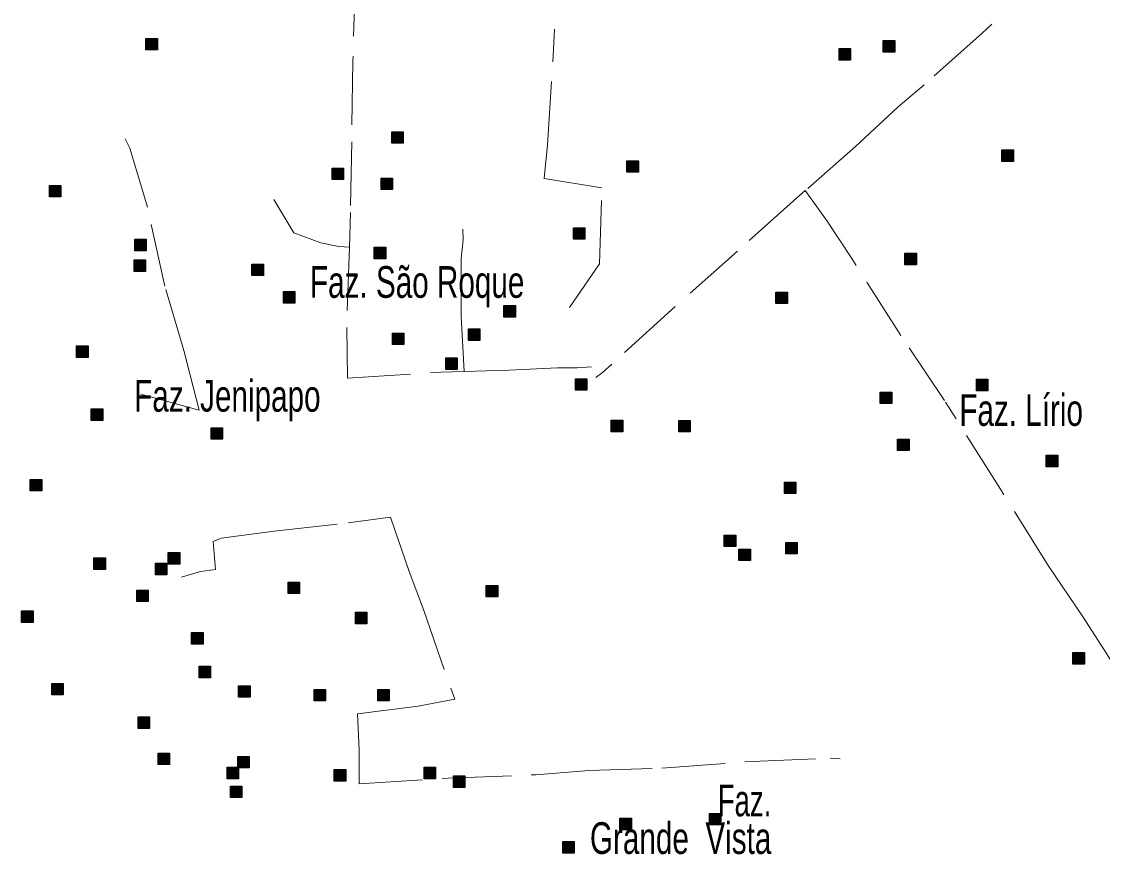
# Model space of a CAD drawing. Extents: x 445.6 to 500, y 8618.1 to 8673.4.
# Drawn here: x 477.45 to 482.9, y 8640.05 to 8644.26 of the extents above; entities that cross this region are included whole.
import ezdxf
from ezdxf.enums import TextEntityAlignment as Align

# ---------------------------------------------------------------- set-up
doc = ezdxf.new("R2010")
doc.units = 0
doc.header["$LTSCALE"] = 0.064
doc.linetypes.add('DOT_DASHED', pattern=[7.7, 5, -1.2, 0.3, -1.2])
doc.layers.add('2', color=7, linetype='Continuous', lineweight=25)
doc.layers.add('22', color=7, linetype='DOT_DASHED', lineweight=13)
doc.layers.add('61', color=7, linetype='Continuous')

msp = doc.modelspace()

# ---------------------------------------------------------------- hatches: boundary and pattern name
at = {"layer": '2'}
for points in [[(478.0733, 8644.173), (478.1313, 8644.173), (478.1313, 8644.115), (478.0733, 8644.115)], [(481.5725, 8644.1218), (481.6305, 8644.1218), (481.6305, 8644.0638), (481.5725, 8644.0638)], [(481.7954, 8644.1625), (481.8534, 8644.1625), (481.8534, 8644.1045), (481.7954, 8644.1045)], [(479.3145, 8643.7016), (479.3725, 8643.7016), (479.3725, 8643.6436), (479.3145, 8643.6436)], [(482.3951, 8643.6102), (482.4531, 8643.6102), (482.4531, 8643.5522), (482.3951, 8643.5522)], [(479.0138, 8643.5186), (479.0718, 8643.5186), (479.0718, 8643.4606), (479.0138, 8643.4606)], [(480.502, 8643.5559), (480.56, 8643.5559), (480.56, 8643.4979), (480.502, 8643.4979)], [(479.2604, 8643.4678), (479.3184, 8643.4678), (479.3184, 8643.4098), (479.2604, 8643.4098)], [(477.5869, 8643.4305), (477.6449, 8643.4305), (477.6449, 8643.3725), (477.5869, 8643.3725)], [(480.2321, 8643.2171), (480.2901, 8643.2171), (480.2901, 8643.1591), (480.2321, 8643.1591)], [(478.0174, 8643.1595), (478.0754, 8643.1595), (478.0754, 8643.1015), (478.0174, 8643.1015)], [(479.2266, 8643.1188), (479.2846, 8643.1188), (479.2846, 8643.0608), (479.2266, 8643.0608)], [(481.9054, 8643.0885), (481.9634, 8643.0885), (481.9634, 8643.0305), (481.9054, 8643.0305)], [(478.014, 8643.0545), (478.072, 8643.0545), (478.072, 8642.9965), (478.014, 8642.9965)], [(478.6085, 8643.0342), (478.6665, 8643.0342), (478.6665, 8642.9762), (478.6085, 8642.9762)], [(478.7673, 8642.8952), (478.8253, 8642.8952), (478.8253, 8642.8372), (478.7673, 8642.8372)], [(481.2535, 8642.892), (481.3115, 8642.892), (481.3115, 8642.834), (481.2535, 8642.834)], [(479.8808, 8642.8242), (479.9388, 8642.8242), (479.9388, 8642.7662), (479.8808, 8642.7662)], [(479.702, 8642.7065), (479.76, 8642.7065), (479.76, 8642.6485), (479.702, 8642.6485)], [(479.3178, 8642.6852), (479.3758, 8642.6852), (479.3758, 8642.6272), (479.3178, 8642.6272)], [(477.7236, 8642.6208), (477.7816, 8642.6208), (477.7816, 8642.5628), (477.7236, 8642.5628)], [(479.587, 8642.5599), (479.645, 8642.5599), (479.645, 8642.5019), (479.587, 8642.5019)], [(480.2422, 8642.4549), (480.3002, 8642.4549), (480.3002, 8642.3969), (480.2422, 8642.3969)], [(482.2658, 8642.4522), (482.3238, 8642.4522), (482.3238, 8642.3942), (482.2658, 8642.3942)], [(481.7804, 8642.3872), (481.8384, 8642.3872), (481.8384, 8642.3292), (481.7804, 8642.3292)], [(477.7979, 8642.3024), (477.8559, 8642.3024), (477.8559, 8642.2444), (477.7979, 8642.2444)], [(478.4025, 8642.2075), (478.4605, 8642.2075), (478.4605, 8642.1495), (478.4025, 8642.1495)], [(480.4228, 8642.2453), (480.4808, 8642.2453), (480.4808, 8642.1873), (480.4228, 8642.1873)], [(480.7637, 8642.2449), (480.8217, 8642.2449), (480.8217, 8642.1869), (480.7637, 8642.1869)], [(481.8682, 8642.15), (481.9262, 8642.15), (481.9262, 8642.092), (481.8682, 8642.092)], [(482.6184, 8642.0687), (482.6764, 8642.0687), (482.6764, 8642.0107), (482.6184, 8642.0107)], [(477.49, 8641.9469), (477.548, 8641.9469), (477.548, 8641.8889), (477.49, 8641.8889)], [(481.2969, 8641.9335), (481.3549, 8641.9335), (481.3549, 8641.8755), (481.2969, 8641.8755)], [(480.9929, 8641.6658), (481.0509, 8641.6658), (481.0509, 8641.6078), (480.9929, 8641.6078)], [(481.3037, 8641.6285), (481.3617, 8641.6285), (481.3617, 8641.5705), (481.3037, 8641.5705)], [(478.186, 8641.5769), (478.244, 8641.5769), (478.244, 8641.5189), (478.186, 8641.5189)], [(481.0672, 8641.5947), (481.1252, 8641.5947), (481.1252, 8641.5367), (481.0672, 8641.5367)], [(477.8109, 8641.5505), (477.8689, 8641.5505), (477.8689, 8641.4925), (477.8109, 8641.4925)], [(478.1216, 8641.5234), (478.1796, 8641.5234), (478.1796, 8641.4654), (478.1216, 8641.4654)], [(478.027, 8641.3879), (478.085, 8641.3879), (478.085, 8641.3299), (478.027, 8641.3299)], [(478.7917, 8641.4287), (478.8497, 8641.4287), (478.8497, 8641.3707), (478.7917, 8641.3707)], [(479.7915, 8641.4118), (479.8495, 8641.4118), (479.8495, 8641.3538), (479.7915, 8641.3538)], [(477.4461, 8641.2829), (477.5041, 8641.2829), (477.5041, 8641.2249), (477.4461, 8641.2249)], [(479.1316, 8641.2761), (479.1896, 8641.2761), (479.1896, 8641.2181), (479.1316, 8641.2181)], [(478.3044, 8641.1733), (478.3624, 8641.1733), (478.3624, 8641.1153), (478.3044, 8641.1153)], [(482.7535, 8641.0727), (482.8115, 8641.0727), (482.8115, 8641.0147), (482.7535, 8641.0147)], [(478.3416, 8641.0037), (478.3996, 8641.0037), (478.3996, 8640.9457), (478.3416, 8640.9457)], [(477.5981, 8640.917), (477.6561, 8640.917), (477.6561, 8640.859), (477.5981, 8640.859)], [(478.5411, 8640.9053), (478.5991, 8640.9053), (478.5991, 8640.8473), (478.5411, 8640.8473)], [(478.9221, 8640.8865), (478.9801, 8640.8865), (478.9801, 8640.8285), (478.9221, 8640.8285)], [(479.2443, 8640.8867), (479.3023, 8640.8867), (479.3023, 8640.8287), (479.2443, 8640.8287)], [(478.0338, 8640.7476), (478.0918, 8640.7476), (478.0918, 8640.6896), (478.0338, 8640.6896)], [(478.1351, 8640.5647), (478.1931, 8640.5647), (478.1931, 8640.5067), (478.1351, 8640.5067)], [(478.5371, 8640.5477), (478.5951, 8640.5477), (478.5951, 8640.4897), (478.5371, 8640.4897)], [(478.483, 8640.4935), (478.541, 8640.4935), (478.541, 8640.4355), (478.483, 8640.4355)], [(479.0246, 8640.4814), (479.0826, 8640.4814), (479.0826, 8640.4234), (479.0246, 8640.4234)], [(479.4774, 8640.4937), (479.5354, 8640.4937), (479.5354, 8640.4357), (479.4774, 8640.4357)], [(479.626, 8640.4496), (479.684, 8640.4496), (479.684, 8640.3916), (479.626, 8640.3916)], [(478.4999, 8640.3987), (478.5579, 8640.3987), (478.5579, 8640.3407), (478.4999, 8640.3407)], [(480.9186, 8640.2599), (480.9766, 8640.2599), (480.9766, 8640.2019), (480.9186, 8640.2019)], [(480.466, 8640.2362), (480.524, 8640.2362), (480.524, 8640.1782), (480.466, 8640.1782)], [(480.1782, 8640.1184), (480.2362, 8640.1184), (480.2362, 8640.0604), (480.1782, 8640.0604)]]:
    msp.add_hatch(color=256, dxfattribs=at).paths.add_polyline_path(points)

# ---------------------------------------------------------------- linework, layer by layer
for points in [[(478.0733, 8644.173), (478.1313, 8644.173), (478.1313, 8644.115), (478.0733, 8644.115)], [(481.5725, 8644.1218), (481.6305, 8644.1218), (481.6305, 8644.0638), (481.5725, 8644.0638)], [(481.7954, 8644.1625), (481.8534, 8644.1625), (481.8534, 8644.1045), (481.7954, 8644.1045)], [(479.3145, 8643.7016), (479.3725, 8643.7016), (479.3725, 8643.6436), (479.3145, 8643.6436)], [(482.3951, 8643.6102), (482.4531, 8643.6102), (482.4531, 8643.5522), (482.3951, 8643.5522)], [(479.0138, 8643.5186), (479.0718, 8643.5186), (479.0718, 8643.4606), (479.0138, 8643.4606)], [(480.502, 8643.5559), (480.56, 8643.5559), (480.56, 8643.4979), (480.502, 8643.4979)], [(479.2604, 8643.4678), (479.3184, 8643.4678), (479.3184, 8643.4098), (479.2604, 8643.4098)], [(477.5869, 8643.4305), (477.6449, 8643.4305), (477.6449, 8643.3725), (477.5869, 8643.3725)], [(480.2321, 8643.2171), (480.2901, 8643.2171), (480.2901, 8643.1591), (480.2321, 8643.1591)], [(478.0174, 8643.1595), (478.0754, 8643.1595), (478.0754, 8643.1015), (478.0174, 8643.1015)], [(479.2266, 8643.1188), (479.2846, 8643.1188), (479.2846, 8643.0608), (479.2266, 8643.0608)], [(481.9054, 8643.0885), (481.9634, 8643.0885), (481.9634, 8643.0305), (481.9054, 8643.0305)], [(478.014, 8643.0545), (478.072, 8643.0545), (478.072, 8642.9965), (478.014, 8642.9965)], [(478.6085, 8643.0342), (478.6665, 8643.0342), (478.6665, 8642.9762), (478.6085, 8642.9762)], [(478.7673, 8642.8952), (478.8253, 8642.8952), (478.8253, 8642.8372), (478.7673, 8642.8372)], [(481.2535, 8642.892), (481.3115, 8642.892), (481.3115, 8642.834), (481.2535, 8642.834)], [(479.8808, 8642.8242), (479.9388, 8642.8242), (479.9388, 8642.7662), (479.8808, 8642.7662)], [(479.702, 8642.7065), (479.76, 8642.7065), (479.76, 8642.6485), (479.702, 8642.6485)], [(479.3178, 8642.6852), (479.3758, 8642.6852), (479.3758, 8642.6272), (479.3178, 8642.6272)], [(477.7236, 8642.6208), (477.7816, 8642.6208), (477.7816, 8642.5628), (477.7236, 8642.5628)], [(479.587, 8642.5599), (479.645, 8642.5599), (479.645, 8642.5019), (479.587, 8642.5019)], [(480.2422, 8642.4549), (480.3002, 8642.4549), (480.3002, 8642.3969), (480.2422, 8642.3969)], [(482.2658, 8642.4522), (482.3238, 8642.4522), (482.3238, 8642.3942), (482.2658, 8642.3942)], [(481.7804, 8642.3872), (481.8384, 8642.3872), (481.8384, 8642.3292), (481.7804, 8642.3292)], [(477.7979, 8642.3024), (477.8559, 8642.3024), (477.8559, 8642.2444), (477.7979, 8642.2444)], [(478.4025, 8642.2075), (478.4605, 8642.2075), (478.4605, 8642.1495), (478.4025, 8642.1495)], [(480.4228, 8642.2453), (480.4808, 8642.2453), (480.4808, 8642.1873), (480.4228, 8642.1873)], [(480.7637, 8642.2449), (480.8217, 8642.2449), (480.8217, 8642.1869), (480.7637, 8642.1869)], [(481.8682, 8642.15), (481.9262, 8642.15), (481.9262, 8642.092), (481.8682, 8642.092)], [(482.6184, 8642.0687), (482.6764, 8642.0687), (482.6764, 8642.0107), (482.6184, 8642.0107)], [(477.49, 8641.9469), (477.548, 8641.9469), (477.548, 8641.8889), (477.49, 8641.8889)], [(481.2969, 8641.9335), (481.3549, 8641.9335), (481.3549, 8641.8755), (481.2969, 8641.8755)], [(480.9929, 8641.6658), (481.0509, 8641.6658), (481.0509, 8641.6078), (480.9929, 8641.6078)], [(481.3037, 8641.6285), (481.3617, 8641.6285), (481.3617, 8641.5705), (481.3037, 8641.5705)], [(478.186, 8641.5769), (478.244, 8641.5769), (478.244, 8641.5189), (478.186, 8641.5189)], [(481.0672, 8641.5947), (481.1252, 8641.5947), (481.1252, 8641.5367), (481.0672, 8641.5367)], [(477.8109, 8641.5505), (477.8689, 8641.5505), (477.8689, 8641.4925), (477.8109, 8641.4925)], [(478.1216, 8641.5234), (478.1796, 8641.5234), (478.1796, 8641.4654), (478.1216, 8641.4654)], [(478.027, 8641.3879), (478.085, 8641.3879), (478.085, 8641.3299), (478.027, 8641.3299)], [(478.7917, 8641.4287), (478.8497, 8641.4287), (478.8497, 8641.3707), (478.7917, 8641.3707)], [(479.7915, 8641.4118), (479.8495, 8641.4118), (479.8495, 8641.3538), (479.7915, 8641.3538)], [(477.4461, 8641.2829), (477.5041, 8641.2829), (477.5041, 8641.2249), (477.4461, 8641.2249)], [(479.1316, 8641.2761), (479.1896, 8641.2761), (479.1896, 8641.2181), (479.1316, 8641.2181)], [(478.3044, 8641.1733), (478.3624, 8641.1733), (478.3624, 8641.1153), (478.3044, 8641.1153)], [(482.7535, 8641.0727), (482.8115, 8641.0727), (482.8115, 8641.0147), (482.7535, 8641.0147)], [(478.3416, 8641.0037), (478.3996, 8641.0037), (478.3996, 8640.9457), (478.3416, 8640.9457)], [(477.5981, 8640.917), (477.6561, 8640.917), (477.6561, 8640.859), (477.5981, 8640.859)], [(478.5411, 8640.9053), (478.5991, 8640.9053), (478.5991, 8640.8473), (478.5411, 8640.8473)], [(478.9221, 8640.8865), (478.9801, 8640.8865), (478.9801, 8640.8285), (478.9221, 8640.8285)], [(479.2443, 8640.8867), (479.3023, 8640.8867), (479.3023, 8640.8287), (479.2443, 8640.8287)], [(478.0338, 8640.7476), (478.0918, 8640.7476), (478.0918, 8640.6896), (478.0338, 8640.6896)], [(478.1351, 8640.5647), (478.1931, 8640.5647), (478.1931, 8640.5067), (478.1351, 8640.5067)], [(478.5371, 8640.5477), (478.5951, 8640.5477), (478.5951, 8640.4897), (478.5371, 8640.4897)], [(478.483, 8640.4935), (478.541, 8640.4935), (478.541, 8640.4355), (478.483, 8640.4355)], [(479.0246, 8640.4814), (479.0826, 8640.4814), (479.0826, 8640.4234), (479.0246, 8640.4234)], [(479.4774, 8640.4937), (479.5354, 8640.4937), (479.5354, 8640.4357), (479.4774, 8640.4357)], [(479.626, 8640.4496), (479.684, 8640.4496), (479.684, 8640.3916), (479.626, 8640.3916)], [(478.4999, 8640.3987), (478.5579, 8640.3987), (478.5579, 8640.3407), (478.4999, 8640.3407)], [(480.9186, 8640.2599), (480.9766, 8640.2599), (480.9766, 8640.2019), (480.9186, 8640.2019)], [(480.466, 8640.2362), (480.524, 8640.2362), (480.524, 8640.1782), (480.466, 8640.1782)], [(480.1782, 8640.1184), (480.2362, 8640.1184), (480.2362, 8640.0604), (480.1782, 8640.0604)]]:
    msp.add_lwpolyline(points, close=True, dxfattribs=at)
at = {"layer": '22'}
for points in [[(484.1191, 8645.8895), (483.8667, 8645.5828), (483.7598, 8645.4913), (483.5461, 8645.3008), (483.2095, 8645.0121), (482.955, 8644.8012), (482.6548, 8644.5268), (482.2926, 8644.1975), (482.0016, 8643.9391), (481.8718, 8643.8273), (481.6555, 8643.6266), (481.4015, 8643.4048)], [(479.1252, 8644.8185), (479.1309, 8644.5039), (479.1186, 8644.0566), (479.1123, 8643.6503), (479.1062, 8643.2949), (479.1005, 8643.1185)], [(480.2117, 8642.8138), (480.3627, 8643.0347), (480.3758, 8643.4182), (480.0834, 8643.4661), (480.1009, 8643.6361), (480.1314, 8644.1173), (480.1368, 8644.2199)], [(478.0485, 8642.3773), (478.3431, 8642.2963), (478.2657, 8642.598), (478.1699, 8642.9217), (478.0815, 8643.3212), (477.9931, 8643.6192), (477.9692, 8643.6661)], [(478.7199, 8643.3592), (478.8196, 8643.1921), (478.956, 8643.1406), (479.0481, 8643.1222), (479.1005, 8643.1185)], [(481.4015, 8643.4048), (481.3571, 8643.3661), (481.0594, 8643.0993), (480.726, 8642.802), (480.4248, 8642.5283), (480.3765, 8642.4851), (480.3446, 8642.4616)], [(483.5996, 8640.1579), (483.4566, 8640.3426), (483.3715, 8640.443), (483.3317, 8640.4257), (483.1731, 8640.6844), (482.9102, 8641.086), (482.8019, 8641.2559), (482.6275, 8641.5127), (482.3874, 8641.897), (482.1051, 8642.3449), (481.8847, 8642.6731), (481.6364, 8643.0614), (481.5127, 8643.2506), (481.4015, 8643.4048)], [(479.6809, 8642.492), (479.6654, 8642.7706), (479.6654, 8643.0617), (479.6746, 8643.1556), (479.6733, 8643.2094)], [(479.1005, 8643.1185), (479.0875, 8642.714), (479.0904, 8642.4581), (479.5628, 8642.4888), (479.6809, 8642.492)], [(479.6809, 8642.492), (479.9064, 8642.498), (480.1519, 8642.5102), (480.2514, 8642.5102), (480.323, 8642.5148)], [(478.2528, 8641.4525), (478.3484, 8641.4813), (478.4253, 8641.4915), (478.4125, 8641.6324), (478.4536, 8641.6503), (478.7204, 8641.6862), (479.095, 8641.7272), (479.3079, 8641.7554), (479.4028, 8641.4813), (479.4747, 8641.2891), (479.6322, 8640.8371), (479.4475, 8640.8012), (479.1422, 8640.7628), (479.1499, 8640.5809), (479.1498, 8640.4098), (479.5988, 8640.438), (480.0427, 8640.4559), (480.3095, 8640.4764), (480.6778, 8640.4895), (481.1345, 8640.5228), (481.528, 8640.5386), (481.5787, 8640.5362)]]:
    msp.add_lwpolyline(points, dxfattribs=at)

# ---------------------------------------------------------------- texts
at = {"layer": '61', "width": 0.7}
for s, p in [('Faz. São Roque', (478.9017, 8642.8635)), ('Faz. Jenipapo', (478.0144, 8642.2887)), ('Faz. Lírio', (482.1797, 8642.217))]:
    msp.add_text(s, height=0.16, dxfattribs=at).set_placement(p)
at = {"layer": '61'}
for s, width, p in [('Faz.', 0.65, (481.2308, 8640.2458)), ('Grande  Vista', 0.7, (481.2308, 8640.0558))]:
    msp.add_text(s, height=0.16, dxfattribs=dict(at, width=width)).set_placement(p, align=Align.RIGHT)

doc.saveas('drawing.dxf')
